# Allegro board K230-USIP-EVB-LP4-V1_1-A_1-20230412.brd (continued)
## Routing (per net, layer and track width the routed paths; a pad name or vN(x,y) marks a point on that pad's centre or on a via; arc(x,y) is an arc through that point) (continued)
MMC1_D0: length 64.5
  TOP w0.127: R123.1 24.89,99.57 24.89,101.22 25.78,102.11 27.43,102.11 27.81,102.49 v1(31.37,102.49) ; v1(68.2,83.19) 67.5,83.89 U4.7
  ART06 w0.127: v1(31.37,102.49) 32,101.85 32.89,101.85 40.13,94.61 63.75,94.61 69.09,89.28 69.09,84.07 v1(68.2,83.19)
  BOTTOM w0.127: R189.2 v1(68.2,83.19) 67.69,83.69 U23.2
MMC1_D1: length 66.4
  TOP w0.127: v1(68.2,81.92) 67.33,82.79 U4.8 ; v1(32.64,101.35) 32.13,100.84 29.59,100.84 R124.1
  ART06 w0.127: v1(68.2,81.92) 67.69,82.42 67.69,83.82 68.71,84.84 68.71,88.9 66.93,90.68 65.91,90.68 62.48,94.11 44.8,94.11 44.65,93.96 44.65,93.24 44.51,93.09 44.3,93.09 44.15,93.24 44.15,93.96 44,94.11 43.79,94.11 43.64,93.96 43.64,93.24 43.49,93.09 43.28,93.09 43.13,93.24 43.13,93.96 42.98,94.11 42.77,94.11 42.62,93.96 42.62,93.24 42.47,93.09 42.26,93.09 42.11,93.24 42.11,93.96 41.97,94.11 41.76,94.11 41.61,93.96 41.61,93.49 41.46,93.34 41.25,93.34 41.1,93.49 41.1,93.96 40.95,94.11 40.01,94.11 32.77,101.35 v1(32.64,101.35)
  BOTTOM w0.127: U23.3 67.69,81.41 v1(68.2,81.92) R190.2
MMC1_D2: length 66.4
  TOP w0.127: v1(67.96,91.31) 67.13,90.49 U4.1 ; R125.1 25.91,99.44 25.91,100.84 26.16,101.09 27.56,101.09 28.45,101.98 32,101.98 v1(32.51,102.49)
  ART06 w0.127: v1(32.51,102.49) 32.89,102.49 33.67,101.71 33.88,101.71 34.5,102.32 34.71,102.32 34.86,102.17 34.86,101.96 34.24,101.35 34.24,101.14 34.39,100.99 34.6,100.99 35.22,101.6 35.43,101.6 35.58,101.46 35.58,101.25 34.96,100.63 34.96,100.42 35.11,100.27 35.32,100.27 35.94,100.89 36.15,100.89 36.3,100.74 36.3,100.53 35.68,99.91 35.68,99.7 35.83,99.55 36.04,99.55 36.66,100.17 36.87,100.17 37.02,100.02 37.02,99.81 36.4,99.19 36.4,98.98 36.55,98.83 36.76,98.83 37.37,99.45 37.58,99.45 37.73,99.3 37.73,99.09 37.12,98.47 37.12,98.26 37.27,98.11 37.48,98.11 38.09,98.73 38.3,98.73 38.45,98.58 38.45,98.37 37.84,97.75 37.84,97.54 40.26,95.12 64.15,95.12 v1(67.96,91.31)
  BOTTOM w0.127: R191.2 68.08,91.44 v1(67.96,91.31) U24.2
MMC1_D3: length 67.1
  TOP w0.127: R126.1 28.96,101.35 v1(31.37,101.35) ; v1(67.82,88.9) 67.33,89.39 U4.2
  ART06 w0.127: v1(67.82,88.9) 66.55,90.17 65.79,90.17 62.36,93.6 51.74,93.6 51.59,93.45 51.59,92.48 51.44,92.33 51.22,92.33 51.07,92.48 51.07,93.45 50.92,93.6 50.7,93.6 50.55,93.45 50.55,92.48 50.4,92.33 50.18,92.33 50.03,92.48 50.03,93.45 49.88,93.6 49.66,93.6 49.51,93.45 49.51,92.48 49.36,92.33 49.14,92.33 48.99,92.48 48.99,93.45 48.84,93.6 48.62,93.6 48.47,93.45 48.47,92.48 48.32,92.33 48.1,92.33 47.95,92.48 47.95,93.45 47.79,93.6 47.58,93.6 47.43,93.45 47.43,92.48 47.27,92.33 47.01,92.33 46.86,92.48 46.86,93.2 46.71,93.34 46.5,93.34 46.35,93.2 46.35,92.48 46.2,92.33 45.99,92.33 45.84,92.48 45.84,93.2 45.69,93.34 45.48,93.34 45.33,93.2 45.33,92.48 45.18,92.33 41.15,92.33 32.77,100.71 32,100.71 v1(31.37,101.35)
  BOTTOM w0.127: U24.3 67.69,89.03 v1(67.82,88.9) R193.2 R147.2
MUTE: length 6.1
  TOP w0.127: TP25.1 62.48,121.16 62.36,121.03 R130.2 61.85,120.52 60.82,121.56 U16.6
NC_NC: length 3.3
  TOP w0.127: R207.2 1.91,38.1
OSPI_CLK: length 43.2
  TOP w0.127: J9.14 28.89,106.36 29.46,106.93 32.26,106.93 32.64,107.31 v1(32.64,113.67) ; U1.K1 28.9,92.02 29.72,92.84 29.72,94.54 v3(29.79,94.61)
  ART06 w0.127: v1(32.64,113.67) 30.99,113.67 30.61,113.28 30.61,109.73 29.95,109.07 29.95,97.13 29.22,96.41 29.22,95.19 v3(29.79,94.61)
OSPI_CS: length 43.9
  TOP w0.127: J9.6 23.18,118.3 25.65,115.82 25.65,111.38 26.29,110.74 27.18,110.74 v1(27.69,111.25) ; U1.J5 v2(29.22,83.26)
  ART06 w0.076: v2(29.22,83.26) 28.24,84.24 28.24,85.6
  ART06 w0.127: 28.24,85.6 28.24,86.39 28.3,86.44 28.3,87.25 27.18,88.37 27.18,97.54 28,98.36 28,108.65 27.69,108.97 v1(27.69,111.25)
OSPI_D0: length 43.3
  TOP w0.076: 29.23,86.49 29.23,85.86 U1.K2
  TOP w0.127: 29.23,86.49 29.23,91.58 30.35,92.71 30.35,95.38 v1(30.86,95.89) ; v1(32,107.57) 29.08,107.57 26.99,105.47 J9.13
  ART06 w0.127: v1(30.86,95.89) 30.77,95.97 30.77,102.91 30.92,103.06 34.27,103.06 34.42,103.21 34.42,103.42 34.27,103.57 30.92,103.57 30.77,103.72 30.77,103.93 30.92,104.08 33.38,104.08 33.53,104.23 33.53,104.44 33.38,104.59 30.92,104.59 30.77,104.74 30.77,105.03 30.9,105.16 31.88,105.16 32,105.28 v1(32,107.57)
OSPI_D1: length 43.4
  TOP w0.127: U1.K4 v2(29.22,84.56) ; v1(28.19,110.36) 26.04,110.36 25.02,111.38 25.02,115.82 21.27,119.57 J9.7
  ART06 w0.076: 28.83,86.11 28.7,85.98 28.7,84.84 28.98,84.56 v2(29.22,84.56)
  ART06 w0.127: 28.83,86.11 28.91,86.18 28.91,87.68 27.93,88.66 27.93,97.14 28.74,97.96 28.74,109.82 v1(28.19,110.36)
OSPI_D2: length 43.1
  TOP w0.127: J9.9 19.37,105.35 20.83,106.81 24,106.81 24.16,106.96 24.16,107.17 23.73,107.6 23.73,107.81 23.88,107.96 24.09,107.96 24.52,107.53 24.73,107.53 24.88,107.68 24.88,107.89 24.45,108.32 24.45,108.53 24.6,108.68 24.81,108.68 25.24,108.25 25.45,108.25 25.6,108.4 25.6,108.61 25.17,109.04 25.17,109.25 25.32,109.4 25.53,109.4 25.96,108.97 26.17,108.97 26.54,109.35 v1(28.19,109.35) ; U1.K5 v2(29.22,83.91)
  ART06 w0.076: v2(29.22,83.91) 28.49,84.65 28.49,86.14 28.57,86.23 28.57,86.36
  ART06 w0.127: v1(28.19,109.35) 28.36,109.18 28.36,98.21 27.56,97.41 27.56,88.52 28.57,87.5 28.57,86.36
OSPI_D3: length 43.1
  TOP w0.127: J9.3 28.89,120.59 29.21,120.27 v1(29.21,114.43) ; v1(28.71,94.61) 28.71,93.26 28.25,92.79 U1.L1
  ART06 w0.127: v1(28.71,94.61) 28.71,96.79 29.44,97.51 29.44,109.58 29.97,110.11 29.97,110.95 29.82,111.1 28.98,111.1 28.83,111.25 28.83,111.46 28.98,111.61 29.82,111.61 29.97,111.76 29.97,111.97 29.82,112.12 28.98,112.12 28.83,112.27 28.83,112.48 28.98,112.63 29.82,112.63 29.97,112.78 29.97,112.99 29.82,113.14 28.98,113.14 28.83,113.28 28.83,113.49 28.98,113.64 29.82,113.64 29.97,113.79 29.97,114.3 29.84,114.43 v1(29.21,114.43)
OSPI_D4: length 43.1
  TOP w0.076: 28.58,86.61 28.58,85.86 U1.L2
  TOP w0.127: J9.12 25.08,105.35 28.57,108.84 v1(32,108.84) ; 28.58,86.61 28.58,92.71 29.21,93.35 29.21,95.25 v1(29.84,95.89)
  ART06 w0.127: v1(32,108.84) 32,112.9 31.88,113.03 31.37,113.03 31.24,112.9 31.24,109.6 30.45,108.81 30.45,96.49 v1(29.84,95.89)
OSPI_D5: length 43
  TOP w0.127: v1(26.67,111.25) 26.16,111.76 26.16,115.95 25.08,117.03 25.08,117.79 25.23,117.94 25.76,117.94 25.91,118.08 25.91,118.3 25.76,118.44 25.23,118.44 25.08,118.59 25.08,118.8 25.23,118.95 25.76,118.95 25.91,119.1 25.91,119.31 25.76,119.46 25.23,119.46 25.08,119.61 25.08,119.82 25.23,119.97 25.76,119.97 25.91,120.12 25.91,120.33 25.76,120.48 25.23,120.48 25.08,120.62 J9.5 ; U1.L3 v2(27.93,85.21)
  ART06 w0.127: v1(26.67,111.25) 26.67,109.47 27.65,108.5 27.65,98.51 26.8,97.66 26.8,88.14 27.93,87.01 v2(27.93,85.21)
OSPI_D6: length 43.2
  TOP w0.127: U1.L4 v2(27.93,84.56) ; J9.10 21.27,106.11 21.46,106.3 21.72,106.3 21.87,106.15 21.87,105.81 22.02,105.66 22.23,105.66 22.38,105.81 22.38,106.15 22.53,106.3 22.74,106.3 22.88,106.15 22.88,105.81 23.03,105.66 23.24,105.66 23.39,105.81 23.39,106.15 23.54,106.3 24.45,106.3 v1(26.35,108.2)
  ART06 w0.076: v2(27.93,84.56) 27.93,84.72 27.6,85.05 27.6,85.47
  ART06 w0.127: 27.6,85.47 27.6,86.74 26.41,87.93 26.41,97.91 27.28,98.78 27.28,103.92 27.13,104.07 26.31,104.07 26.16,104.21 26.16,104.42 26.31,104.57 27.13,104.57 27.28,104.72 27.28,104.93 27.13,105.08 26.31,105.08 26.16,105.23 26.16,105.44 26.31,105.59 27.13,105.59 27.28,105.74 27.28,105.95 27.13,106.1 26.31,106.1 26.16,106.25 26.16,106.46 26.31,106.61 27.13,106.61 27.28,106.75 27.28,106.96 27.13,107.11 26.31,107.11 26.16,107.26 26.16,107.47 26.31,107.62 27.13,107.62 27.28,107.77 27.28,107.98 27.05,108.2 v1(26.35,108.2)
OSPI_D7: length 43.1
  TOP w0.127: v1(26.99,112.65) J9.4 ; U1.L5 v2(27.93,83.91)
  ART06 w0.076: v2(27.93,83.91) 27.93,84.01 27.6,84.34 27.6,84.7 27.3,84.99 27.3,85.34
  ART06 w0.127: v1(26.99,112.65) 26.99,113.22 26.8,113.41 26.04,113.41 25.78,113.16 25.78,103.76 25.91,103.63 26.8,103.63 26.92,103.5 26.92,98.93 26.01,98.02 26.01,87.78 27.3,86.49 27.3,85.34
OSPI_DQS: length 43.2
  TOP w0.127: U1.L6 v2(27.93,83.26) ; J9.11 v1(23.18,99.82)
  ART06 w0.076: v2(27.93,83.26) 27.59,83.6 27.59,84.04 27.39,84.24 27.14,84.24 26.94,84.44 26.94,85.58
  ART06 w0.127: 26.94,85.58 26.94,86.36 25.69,87.61 25.69,96.62 25.46,96.84 22.39,96.84 22.25,96.99 22.25,97.2 22.39,97.35 25.54,97.35 25.66,97.48 25.66,97.66 25.46,97.86 22.39,97.86 22.25,98.01 22.25,98.22 22.39,98.36 25.56,98.36 25.69,98.49 25.69,98.9 25.53,99.06 22.35,99.06 22.23,99.19 22.23,101.6 22.35,101.73 22.86,101.73 22.99,101.6 22.99,100.01 v1(23.18,99.82)
OTP_IO59: length 3.7
  TOP w0.127: U34.3 59.98,98.46 J22.2
OUT: length 4
  TOP w0.127: U29.4 TVS14.1 70.36,134.87 70.74,134.49 71.63,134.49
OUTL+: length 16.2
  TOP w0.127: U16.2 57.92,119.77 v1(57.53,119.38)
  BOTTOM w0.127: R82.1 62.22,129.92 60.46,129.92 57.02,126.48 57.02,119.89 v1(57.53,119.38)
OUTL-: length 18.8
  TOP w0.127: U16.5 59.42,119.78 v1(59.82,119.38)
  BOTTOM w0.127: R84.1 60.45,130.56 56.64,126.75 56.64,119.51 57.28,118.87 59.31,118.87 v1(59.82,119.38)
OUTR+: length 7.8
  TOP w0.127: R86.1 61.98,130.19 61.98,129.41 57.92,125.36 U16.14
OUTR-: length 7.4
  TOP w0.127: U16.11 59.42,125.08 59.94,125.6 59.94,126.87 62.48,129.41 62.48,130.18 R90.1
PW_EN: length 10.7
  TOP w0.254: C268.1 14.1,4.32 16.51,1.91 19.05,1.91
PWIN_FLASH: length 48.8
  TOP w0.127: J9.8 19.37,120.78 24.51,115.63 24.51,111.25 25.91,109.86 28.83,109.86 v1(29.34,110.36) ; U1.K7 v2(29.22,81.96)
  ART06 w0.127: v2(28.32,93.73) 28.22,93.83 28.22,96.8 29.08,97.66 29.08,110.11 v1(29.34,110.36)
  BOTTOM w0.127: v2(28.32,93.73) 27.81,93.22 27.81,86.49 27.94,86.36 C27.1 28.32,82.86 v2(29.22,81.96)
RESET_N_A_B: length 44
  TOP w0.089: U1.J16 v2(29.87,76.11)
  ART03 w0.086: v2(29.87,76.11) 29.87,75.67 29.34,75.14 28.45,75.14 28.25,74.94 28.25,72.66 28.65,72.26 28.65,49.01 v2(27.83,48.18) 28.14,47.87 39.41,47.87 v2(39.73,48.18)
  BOTTOM w0.086: R64.2 27.83,48.15 v2(27.83,48.18) ; v2(39.73,48.18) 39.88,48.03 R68.2
RTC_1V8: length 123.9
  TOP w0.254: U1.F15 v2(31.82,77.41) U1.F14
  TOP w0.381: R262.2 v1(71.25,25.91) ; R62.2 17.78,3.81 18.41,3.17 22.86,3.17 24.13,1.91 26.67,1.91 27.94,3.17 30.48,3.17 31.75,1.91
  TOP w0.508: v1(49.78,55.12) 47.55,57.35
  ART06 w0.508: v1(49.78,55.12) 50.47,54.43 63.55,54.43 72.95,45.03 72.95,30.66 71.25,28.96 v1(71.25,25.91) 71.25,25.15 63.37,17.27 49.53,17.27 35.43,3.17 33.02,3.17 31.75,1.91
  vias: v1(44.45,58.42) v1(45.72,58.42) v1(45.72,57.15)
RTC_CLK_IN: length 16
  TOP w0.076: U1.B12 34.42,79.36 34.92,79.36
  TOP w0.127: 47.37,74.68 40.44,74.68 38.61,76.5 38.61,77.62 36.87,79.36 34.92,79.36
RTC_CLK_OUT: length 15.8
  TOP w0.127: U1.A12 36.83,79.04 38.23,77.64 38.23,76.16 40.22,74.17 46.61,74.17 47.37,73.41
RTC_INT0: length 93.1
  TOP w0.102: U1.C10 33.77,80.01 v2(33.77,79.36)
  TOP w0.127: v1(35.94,11.18) TVS1.1 34.42,10.41 34.04,10.03
  ART06 w0.127: v2(33.77,79.36) 34.17,79.76 38.61,79.76 40.25,78.12 42.41,78.12 42.8,77.72 46.61,77.72 47.75,76.58 47.75,75.31 49.28,73.79 49.28,71.25 50.29,70.23 50.29,58.8 48.44,56.95 48.44,47.29 47.75,46.61 47.75,44.96 46.35,43.56 46.35,41.53 45.97,41.15 45.17,41.15 43.39,39.37 41.15,39.37 38.48,36.7 38.48,13.72 v1(35.94,11.18)
RTC_INT1: length 93.4
  TOP w0.076: U1.B10 34.42,80.66 35.05,80.66
  TOP w0.127: 31.75,10.03 32.13,10.41 TVS2.1 v1(32.89,11.18) ; 35.05,80.66 37.15,80.66 37.71,80.1 38.6,80.1 39.12,79.58 39.12,78.99 40.39,77.72 40.39,77.39 41.33,76.45 44.96,76.45 v3(45.59,77.09)
  ART06 w0.127: v1(32.89,11.18) 34.54,11.18 37.97,14.61 37.97,36.96 41.66,40.64 42.98,40.64 47.37,45.03 47.37,46.74 48.13,47.5 48.13,57.15 49.91,58.93 49.91,70.07 49,70.98 49,73.56 47.37,75.18 47.37,76.45 46.74,77.09 v3(45.59,77.09)
RTC_INT2: length 93.8
  TOP w0.127: v3(46.61,76.45) 45.47,76.45 45.09,76.07 41.02,76.07 39.88,77.22 39.88,77.72 38.73,78.87 38.73,79.5 38.46,79.78 37.64,79.78 37.09,80.34 U1.A10 ; v1(30.48,11.18) TVS6.1 29.59,10.41 29.21,10.03
  ART06 w0.127: v1(30.48,11.18) 31.11,11.81 34.42,11.81 37.47,14.86 37.47,37.08 41.53,41.15 43,41.15 47.03,45.17 47.03,47.03 47.75,47.75 47.75,57.28 49.53,59.05 49.53,69.98 48.72,70.79 48.72,73.33 47.05,74.99 47.05,76.01 v3(46.61,76.45)
RTC_INT3: length 94.8
  TOP w0.127: 26.67,10.03 27.05,10.41 TVS7.1 v1(27.94,11.18) ; v3(46.61,75.56) 46.28,75.23 40.6,75.23 39.03,76.81 39.03,77.57 36.91,79.69 U1.A11
  ART06 w0.127: v3(46.61,75.56) 46.61,74.93 48.39,73.15 48.39,70.61 49.19,69.81 49.19,59.22 47.41,57.44 47.41,47.92 46.67,47.18 46.67,45.28 43.05,41.66 41.4,41.66 36.96,37.21 36.96,14.99 34.16,12.19 28.96,12.19 v1(27.94,11.18)
RTC_INT4: length 95.7
  TOP w0.076: U1.C12 33.77,78.71 35.69,78.71
  TOP w0.127: 24.13,10.03 24.51,10.41 TVS8.1 v1(25.4,13.34) ; v3(46.35,73.41) 46.1,73.66 39.92,73.66 37.72,75.86 37.72,77.77 36.78,78.71 35.69,78.71
  ART06 w0.127: v1(25.4,13.34) 33.27,13.34 35.43,15.49 35.43,37.59 41.02,43.18 42.16,43.18 42.42,43.43 42.42,44.45 46.45,48.48 46.45,58.13 47.49,59.17 47.49,71.13 46.74,71.88 46.74,73.03 v3(46.35,73.41)
RTC_INT5: length 100.8
  TOP w0.127: 21.59,10.03 21.97,10.41 TVS9.1 v1(22.86,11.18) ; v2(33.12,78.71) 32.8,79.03 U1.D12
  ART06 w0.127: v2(33.12,78.71) 34.01,78.71 34.79,79.49 38.37,79.49 41.34,76.52 45.53,76.52 46.1,75.95 46.1,74.93 48.04,72.99 48.04,70.45 48.77,69.72 48.77,59.31 47.12,57.66 47.12,48.13 46.35,47.37 46.35,45.38 43.14,42.16 41.27,42.16 36.45,37.34 36.45,15.11 33.91,12.57 28.07,12.57 26.67,11.18 v1(22.86,11.18)
RTC_OUT0: length 102.1
  TOP w0.076: U1.B11 34.42,80.01 34.92,80.01
  TOP w0.127: v3(45.59,75.69) 40.77,75.69 39.5,76.96 39.5,77.62 38.35,78.77 38.35,79.34 38.23,79.46 37.58,79.46 37.03,80.01 34.92,80.01 ; v1(20.32,11.18) TVS10.1 19.43,10.41 19.05,10.03 17.78,10.03
  ART06 w0.127: v3(45.59,75.69) 45.59,74.93 47.76,72.76 47.76,58.94 46.79,57.96 46.79,48.31 44.07,45.59 44.07,43.81 42.93,42.67 41.15,42.67 35.94,37.47 35.94,15.37 33.53,12.95 27.56,12.95 26.67,12.06 21.21,12.06 v1(20.32,11.18)
RTC_OUT1: length 62.6
  TOP w0.127: U1.C11 v2(33.12,79.36)
  ART06 w0.127: v2(33.12,79.36) 33.77,80.01 39.24,80.01 40.14,79.11 48.27,79.11 50.67,76.71 56.39,76.71 62.36,70.74 62.36,70.1 63.37,69.09 63.37,62.1 65.41,60.07 66.67,60.07 67.56,59.18 67.56,53.59 71.25,49.91 v1(73.79,49.91)
  BOTTOM w0.127: v1(73.79,49.91) R22.1
SDL: length 5.9
  TOP w0.127: U16.7 61.33,122.06 61.59,121.79 R80.2 62.36,122.3 62.48,122.43 65.28,122.43 TP26.1
SDR: length 6.1
  TOP w0.127: U16.8 61.85,122.56 R132.2 62.36,123.57 62.48,123.7 65.02,123.7 TP27.1
SP_L: length 25.5
  TOP w0.127: C309.1 51.56,121.16 48.51,118.11 48.51,99.69 J20.1
SP_R: length 30
  TOP w0.127: C311.1 48.01,118.36 48.01,97.66 J21.1
SYS_CLK_IN: length 15.2
  TOP w0.076: U1.B8 34.42,81.96 35.05,81.96
  TOP w0.127: 47.37,80.26 46.99,79.88 46.39,79.88 45.89,80.39 45.89,81.24 44.82,82.31 39.38,82.31 39.14,82.07 35.84,82.07 35.73,81.96 35.05,81.96
SYS_CLK_OUT: length 14.3
  TOP w0.127: U1.A8 36.3,81.64 36.46,81.8 44.56,81.8 45.38,80.99 45.38,80.18 46.18,79.38 46.99,79.38 47.37,78.99
SYS_ON_OFF: length 52.5
  TOP w0.127: v1(72.26,22.23) 72.26,23.15 K1.1
  ART06 w0.127: 34.29,1.91 35.56,1.91 50.04,16.38 66.42,16.38 v1(72.26,22.23)
SYS_RST: length 70.6
  TOP w0.076: U1.B9 34.42,81.31 35.05,81.31
  TOP w0.127: 35.05,81.31 37.44,81.31 37.68,81.06 39.78,81.06 40.01,81.29 44.31,81.29 44.83,80.77 44.83,79.92 46.43,78.32 v1(46.58,78.32) ; K2.2 v1(76.83,47.75)
  ART06 w0.127: v1(46.58,78.32) 46.77,78.32 48.86,76.24 48.86,74.97 49.78,74.04 49.78,71.5 50.16,71.12 60.58,71.12 62.87,68.83 62.87,61.85 65.24,59.47 66.51,59.47 67.06,58.93 67.06,53.34 72.64,47.75 v1(73.91,47.75)
  BOTTOM w0.127: v1(73.91,47.75) R223.1 74.8,48.9 75.82,48.9 76.2,48.51 TVS3.1 v1(76.83,47.75)
SYS_SW: length 1.4
  TOP w0.127: 15.24,10.03 15.62,10.41 TVS11.1
TEST_EN: length 15.6
  TOP w0.127: 47.37,76.58 47.37,77.72 46.3,77.72 44.32,79.71 44.32,80.52 44.06,80.78 37.58,80.78 37.38,80.99 U1.A9
TOUCH_INT: length 18.5
  TOP w0.127: R182.1 6.22,84.45 4.95,83.19 3.3,83.19 2.35,84.14 2.35,89.98 5.78,93.41 7.09,93.41 7.09,93.41 J4.10
TOUCH_RST: length 20
  TOP w0.127: R183.1 6.48,82.55 3.18,82.55 1.84,83.88 1.84,90.2 5.56,93.91 7.09,93.91 7.09,93.91 J4.11
U_3V3: length 1.7
  TOP w0.305: 58.04,92.08 57.4,92.08 57.02,91.69 57.02,91.19
UART0_RXD: length 57.6
  TOP w0.127: R54.2 v1(50.29,124.33) ; v1(65.53,116.71) 65.53,116.84 65.69,116.99 U25.6
  ART06 w0.127: v1(50.29,124.33) 49.78,123.83 46.61,123.83 40.01,117.22 40.01,116.46 38.86,115.32 38.86,108.33 v1(38.61,108.08)
  BOTTOM w0.127: v1(65.53,116.71) 64.44,117.81 55.42,117.81 50.29,122.94 v1(50.29,124.33) ; v1(38.61,108.08) 36.07,108.08 33.27,105.28 33.27,104.14 32,102.87 32,99.19 R94.2
UART0_RXD_3V3: length 7.4
  TOP w0.127: U26.16 66.42,112.23 68.78,114.59 68.78,116.64 68.43,116.99 U25.9
UART0_TXD: length 57.5
  TOP w0.127: R53.2 v1(49.15,124.33) ; v1(38.1,106.93) 35.94,106.93 33.91,104.9 33.91,100.58 R92.2 ; U25.5 65.2,117.39 v1(64.64,116.84)
  ART06 w0.127: v1(49.15,124.33) 46.48,124.33 38.48,116.33 38.48,110.36 38.1,109.98 v1(38.1,106.93)
  BOTTOM w0.127: v1(49.15,124.33) 49.15,123.06 54.86,117.35 64.14,117.35 v1(64.64,116.84)
UART0_TXD_3V3: length 9.5
  TOP w0.127: v1(68.2,114.81) 67.31,113.92 64.77,113.92 64.46,113.61 U26.17 ; U25.10 68.53,117.39 69.47,116.46 v1(69.47,114.81)
  BOTTOM w0.127: v1(69.47,114.81) v1(68.2,114.81)
UART3_CTS_FT: length 2.1
  TOP w0.127: U36.10 55.19,108.77 55.23,108.73 U26.40
UART3_RTS_FT: length 2.1
  TOP w0.127: U26.41 55.35,108.23 55.21,108.37 U36.9
UART3_RXD: length 94.6
  TOP w0.127: v1(13.46,71.5) 10.16,68.2 R141.2 ; U36.3 51.98,109.57 51.31,110.24 v1(51.31,110.49)
  ART06 w0.127: v1(26.42,100.58) 24.64,102.36 24.64,114.14 26.83,116.33 v1(27.94,116.33)
  BOTTOM w0.127: v1(51.31,110.49) 50.04,111.76 50.04,113.89 45.66,118.27 30.64,118.27 28.7,116.33 v1(27.94,116.33) ; v1(13.46,71.5) 14.03,72.07 14.03,73.14 20.32,79.43 20.32,98.42 22.86,100.97 26.04,100.97 v1(26.42,100.58) 27.69,99.31 R117.1
UART3_RXD_FT: length 2.1
  TOP w0.127: U26.38 55.37,109.73 55.21,109.57 U36.12
UART3_TXD: length 97.1
  TOP w0.127: U36.4 51.62,109.17 v1(51.31,109.47) ; R144.2 9.78,67.06 14.61,71.88 v1(14.61,72.39)
  ART06 w0.127: v1(26.42,99.69) 24.26,101.85 24.26,114.43 27.18,117.35 v1(28.7,117.35)
  BOTTOM w0.127: v1(51.31,109.47) 51.94,110.11 51.94,110.74 50.42,112.27 50.42,114.05 45.82,118.65 30,118.65 v1(28.7,117.35) ; v1(14.61,72.39) 14.61,73.02 20.78,79.2 20.78,98.25 22.99,100.46 25.65,100.46 v1(26.42,99.69) 26.54,99.57 R115.1
UART3_TXD_FT: length 2.1
  TOP w0.127: U26.39 55.38,109.23 55.32,109.17 U36.11
USB0_DN: length 61.4
  TOP w0.102: U1.B2 34.42,85.86 35.18,85.86
  TOP w0.14: 35.18,85.86 37.94,88.61 41.54,88.61 v3(41.66,88.73) ; 71.46,73.53 71.46,72.8 71.73,72.53 J11.B7 ; 71.46,73.53 71.38,73.61 71.07,73.61 70.06,72.6 67.77,72.6 67.63,72.46 ; 71.46,73.53 72.53,73.53 J11.A7 ; 67.63,72.46 U32.3 ; 67.63,72.46 67.49,72.6 66.42,72.6 v1(66.17,72.35)
  ART06 w0.14: v1(66.17,72.35) 66.38,72.56 67.07,72.56 67.82,73.31 67.82,79.12 66.85,80.09 66.85,85.77 63.34,89.28 54.86,89.28 53.73,90.42 44.22,90.42 42.45,88.65 41.74,88.65 v3(41.66,88.73)
USB0_DP: length 62.4
  TOP w0.14: J11.A6 73.38,73.03 73.52,73.17 73.52,73.89 73.38,74.03 J11.B6 71.62,74.03 71.54,73.95 70.93,73.95 69.92,72.94 67.77,72.94 67.63,73.08 ; U1.A2 34.76,85.52 35.32,85.52 36.04,86.24 36.35,86.24 36.64,86.53 36.64,86.84 38.08,88.27 38.47,88.27 38.73,88.01 39.03,88.01 39.29,88.27 39.59,88.27 39.85,88.01 40.14,88.01 40.41,88.27 41.52,88.27 41.66,88.13 v3(41.66,87.97) ; v1(66.17,73.36) 66.59,72.94 67.49,72.94 67.63,73.08 ; 67.63,73.08 U32.2
  ART06 w0.14: v1(66.17,73.36) 66.17,73.15 66.42,72.9 66.93,72.9 67.48,73.45 67.48,73.95 67.32,74.11 67.12,74.11 66.95,74.27 66.95,74.5 67.12,74.67 67.32,74.67 67.48,74.83 67.48,78.98 66.51,79.95 66.51,85.63 63.2,88.94 54.72,88.94 53.59,90.08 44.36,90.08 42.59,88.31 41.8,88.31 41.66,88.17 v3(41.66,87.97)
USB0_ID: length 59.1
  TOP w0.127: U1.D3 v2(33.12,85.21) ; v1(66.17,75.69) U33.3 67.63,76.58 67.75,76.71 69.98,76.71 71.66,75.03 J11.B5 73.43,75.03 74.3,74.17 74.3,72.77 73.55,72.03 J11.A5
  ART06 w0.127: v2(33.12,85.21) 35.16,87.25 43.43,87.25 45.59,89.41 48.26,89.41 51.44,86.23 63.5,86.23 65.79,83.95 65.79,78.61 66.17,78.23 v1(66.17,75.69)
USB0_OTG_EN: length 116.4
  TOP w0.127: U3.4 66.74,69.41 v1(66.42,69.09) 65.91,68.58 v1(62.23,68.58)
  ART06 w0.127: v1(42.42,38.86) 43.37,38.86 45.28,40.77 46.86,40.77 47.62,41.53 47.62,43.43 48.01,43.81 48.51,43.81 48.77,44.07 48.77,56.64 50.42,58.29 51.05,58.29 51.44,58.67 51.44,59.82 55.24,63.63 57.28,63.63 v1(62.23,68.58)
  BOTTOM w0.127: v1(42.42,38.86) 21.59,38.86 13.46,46.99 13.46,61.09 5.71,68.83 3.94,68.83 3.3,69.47 3.3,76.07 J5.1 ; R41.1 v1(66.42,69.09)
USB0_OTG_VBUS: length 6.1
  TOP w0.381: U3.1 v1(68.96,67.5)
  BOTTOM w0.381: v1(71.12,70.74) 71.12,69.66 v1(68.96,67.5) 68.77,67.69 C17.1
USB0_VBUS: length 15.6
  TOP w0.254: U1.C3 v2(33.77,85.21)
  ART06 w0.254: v2(33.77,85.21) 35.28,86.72 43.42,86.72 44.97,88.27 45.72,88.27 v1(46.35,87.63)
  BOTTOM w0.254: 47.37,87.5 46.48,87.5 v1(46.35,87.63)
USB1_DN: length 63.6
  TOP w0.14: J13.A7 71.33,61.46 ; 71.33,61.46 71.33,60.8 71.67,60.46 J13.B7 ; 71.33,61.46 71.25,61.55 70.93,61.55 69.91,62.57 67.77,62.57 67.63,62.43 ; 67.63,62.43 U31.3 ; 67.63,62.43 67.49,62.57 66.38,62.57 66.17,62.36 v1(66.17,62.19) ; U1.A4 34.76,84.22 36.98,84.22 38.45,85.69 42.77,85.69 42.97,85.89 43.2,85.89 43.33,85.77 43.52,85.77 43.72,85.97 43.72,86.16 43.6,86.29 43.6,86.52 43.86,86.78 44.56,86.78 44.91,86.43 v3(44.91,86.32)
  ART06 w0.14: v3(44.91,86.32) 45.21,86.62 46.63,86.62 47.49,85.77 49.52,85.77 50.79,84.5 60.41,84.5 64.05,80.86 64.05,72.85 65.16,71.75 65.16,62.9 65.49,62.57 65.99,62.57 66.17,62.39 v1(66.17,62.19)
USB1_DP: length 64.3
  TOP w0.102: U1.B4 34.42,84.56 35.19,84.56
  TOP w0.14: J13.A6 73.39,60.96 73.53,61.1 73.53,61.82 73.39,61.96 J13.B6 71.62,61.96 71.54,61.88 71.07,61.88 70.05,62.91 67.77,62.91 67.63,63.05 ; 35.19,84.56 36.84,84.56 38.31,86.03 42.63,86.03 43.72,87.12 44.7,87.12 v3(44.91,87.33) ; 67.63,63.05 U31.2 ; 67.63,63.05 67.49,62.91 66.47,62.91 v1(66.17,63.2)
  ART06 w0.14: v3(44.91,87.33) 44.91,87.13 45.09,86.96 46.77,86.96 47.62,86.11 49.66,86.11 50.93,84.84 60.55,84.84 64.39,81 64.39,72.99 65.49,71.89 65.49,63.04 65.63,62.9 65.87,62.9 v1(66.17,63.2)
USB1_ID: length 73.6
  TOP w0.076: U1.B3 34.42,85.21 35.31,85.21
  TOP w0.127: v1(65.15,77.98) U33.2 67.63,78.74 67.88,78.99 74.68,78.99 76.07,77.6 76.07,64.97 74.07,62.96 ; 74.07,62.96 74.55,62.48 74.55,60.58 73.93,59.96 J13.A5 ; 74.07,62.96 J13.B5 ; v1(46.35,88.9) 43.69,88.9 42.04,87.25 38.35,87.25 36.31,85.21 35.31,85.21
  ART06 w0.127: v1(46.35,88.9) 48.39,86.87 50.29,86.87 51.31,85.85 60.96,85.85 65.15,81.66 v1(65.15,77.98)
USB1_OTG_EN: length 109.9
  TOP w0.127: v1(66.29,58.8) 66.74,59.25 U6.4
  ART06 w0.127: v1(66.29,58.8) 66.04,58.55 52.7,58.55 51.18,57.02 50.42,57.02 49.28,55.88 49.28,46.99 49.78,46.48 49.78,42.55 48.51,41.27 47.88,41.27 46.99,40.39 45.47,40.39 43.43,38.35 v1(41.02,38.35)
  BOTTOM w0.127: v1(41.02,38.35) 21.38,38.35 12.95,46.78 12.95,60.83 5.46,68.33 3.68,68.33 2.92,69.09 2.92,73.91 1.91,74.93 ; v1(66.29,58.8) 66.04,59.05 R46.1
USB1_OTG_VBUS: length 9.6
  TOP w0.381: U6.1 v1(69.02,57.34)
  BOTTOM w0.381: v1(71.12,63.63) v1(71.12,58.8) 69.66,57.34 v1(69.02,57.34) 68.71,57.66 C21.1
USB1_VBUS: length 14.3
  TOP w0.254: U1.A3 36.5,84.89 38.44,86.83 42.25,86.83 43.69,88.27 46.61,88.27 47.37,87.5
VCM: length 2.3
  TOP w0.254: U1.F3 v2(31.17,84.56)
  BOTTOM w0.305: C149.1 30.99,84.75 v2(31.17,84.56)
VSY0: length 8.3
  TOP w0.127: J3.53 45.76,128.61 47,127.37 49.29,127.37 R54.1 R52.2
VTEST: length 15.6
  TOP w0.127: U1.D8 v2(33.12,81.96) ; V-TS.1 v1(46.48,80.64)
  ART06 w0.127: v1(46.48,80.64) 46.35,80.77 41.02,80.77 40.01,81.79 33.3,81.79 v2(33.12,81.96)
N20962780: length 3.6
  TOP w0.254: Y1.1 50.43,73.79 49.91,73.79 C3.1 R5.2
N20962782: length 3.7
  TOP w0.254: Y1.2 50.39,74.25 49.96,74.25 C4.1 R6.1
N20963869: length 2.7
  TOP w0.127: SW1.3 v1(70.48,46.48)
  BOTTOM w0.127: R13.1 v1(70.48,46.48)
N20963881: length 2.7
  TOP w0.127: 67.94,44.89 v1(67.94,46.48)
  BOTTOM w0.127: R14.1 v1(67.94,46.48)
N20968799: length 2.2
  TOP w0.089: U1.K19 v2(28.58,74.16)
  BOTTOM w0.127: R61.1 27.69,73.27 v2(28.57,74.16)
N20974230: length 16.5
  TOP w0.127: v1(46.48,85.22) 46.48,85.47 47.37,86.36 ; U1.D4 v2(33.12,84.56)
  ART06 w0.076: v2(33.12,84.56) 33.44,84.87 33.95,84.87
  ART06 w0.127: 33.95,84.87 34.18,84.87 35.67,86.36 43.94,86.36 44.83,85.47 46.23,85.47 v1(46.48,85.22)
N20974244: length 15.4
  TOP w0.127: U1.C4 v2(33.77,84.56) ; v1(45.09,84.86) 45.22,84.72 46.88,84.72 47.37,85.22
  ART06 w0.127: v2(33.77,84.56) 34.41,84.56 35.83,85.98 43.69,85.98 44.81,84.86 v1(45.09,84.86)
N20974837: length 2.1
  TOP w0.254: U3.3 69.02,69.41 v1(68.96,69.34)
  BOTTOM w0.254: R40.2 68.71,69.09 v1(68.96,69.34)
N20975021: length 2
  TOP w0.254: U6.3 v1(68.96,59.25)
  BOTTOM w0.254: R45.2 68.77,59.05 v1(68.96,59.25)
N20990724: length 3.3
  TOP w0.254: R10.1 C11.1 49.78,80.01 50.55,80.01 Y3.3
N20990759: length 5.2
  TOP w0.254: R8.1 C8.1 50.04,79.5 52.07,79.5 52.87,78.7 Y3.1
N21006529: length 2.8
  TOP w0.127: U1.U6 v2(24.03,83.26)
  BOTTOM w0.127: R65.2 23.5,84.45 24.03,83.92 v2(24.03,83.26)
N21013358: length 17.2
  TOP w0.076: 20,78.06 22.73,78.06 U1.W14
  TOP w0.127: R77.2 8.76,73.41 14.29,73.41 18.94,78.06 20,78.06
N21013362: length 22.5
  TOP w0.127: U1.U12 v2(24.03,79.36) ; v1(10.92,72.77) 9.78,71.63 R79.2
  ART06 w0.076: 22.54,79.95 23.01,79.48 23.76,79.48 23.88,79.36 v2(24.03,79.36)
  ART06 w0.127: 22.54,79.95 22.22,80.26 16.76,80.26 16.26,79.76 15.24,79.76 13.46,77.98 12.32,77.98 11.68,77.34 11.68,75.82 10.92,75.06 v1(10.92,72.77)
N21013366: length 22.4
  TOP w0.127: U1.T13 v2(24.68,78.71)
  ART06 w0.076: 22.35,79.76 22.85,79.26 23.66,79.26 23.89,79.03 24.35,79.03 v2(24.68,78.71)
  ART06 w0.127: 22.35,79.76 22.23,79.88 17.02,79.88 16.51,79.38 15.37,79.38 13.34,77.34 v1(12.45,77.34)
  BOTTOM w0.127: R81.2 7.11,81.53 7.37,81.28 9.78,81.28 11.81,79.25 11.81,77.98 v1(12.45,77.34)
N21013370: length 18.5
  TOP w0.127: U1.U13 v2(24.03,78.71) ; R83.2 8.76,76.71 12.06,76.71 v1(12.57,76.2)
  ART06 w0.076: v2(24.03,78.71) 23.91,78.71 23.58,79.03 22.73,79.03 22.53,79.24
  ART06 w0.127: 22.53,79.24 22.26,79.5 17.14,79.5 16.69,79.04 15.54,79.04 12.7,76.2 v1(12.57,76.2)
N21013374: length 17.3
  TOP w0.127: R85.2 9.4,70.48 11.81,72.9 14.24,72.9 19.08,77.74 U1.Y14
N21013378: length 16.6
  TOP w0.127: R87.2 8.64,77.98 14.61,77.98 v3(15.37,77.22) ; U1.V13 v2(23.38,78.06)
  ART06 w0.127: v3(15.37,77.22) 15.37,77.23 16.17,78.03 23.35,78.03 v2(23.38,78.06)
N21013382: length 20
  TOP w0.127: R89.2 v1(11.05,76.2) ; U1.T12 v2(24.68,79.36)
  ART06 w0.076: v2(24.68,79.36) 24.34,79.69 23.18,79.69 22.8,80.07
  ART06 w0.127: v1(11.05,76.2) 11.05,77.34 12.19,78.49 13.49,78.49 15.09,80.09 16.08,80.09 16.64,80.64 22.22,80.64 22.8,80.07
N21014154: length 18.4
  TOP w0.127: R116.1 9.4,78.36 14.99,78.36 v3(16.13,77.22) ; U1.T14 v2(24.68,78.06)
  ART06 w0.076: 23.04,77.74 24.35,77.74 v2(24.68,78.06)
  ART06 w0.127: 23.04,77.74 16.65,77.74 v3(16.13,77.22)
N21014156: length 20.3
  TOP w0.127: R118.1 8.89,69.34 11.94,72.39 v1(13.46,72.39) ; U1.U15 v2(24.68,77.41)
  ART06 w0.076: v2(24.68,77.41) 24.35,77.09 22.98,77.09
  ART06 w0.127: v1(13.46,72.39) 18.16,77.09 22.98,77.09
N21014379: length 15.1
  TOP w0.127: v1(30.86,93.47) 31.37,93.98 31.37,97.03 R92.1 ; U1.J4 v2(29.87,84.56)
  ART06 w0.076: 29.55,85.81 29.55,85 29.87,84.68 v2(29.87,84.56)
  ART06 w0.127: 29.55,85.81 29.55,90.26 30.86,91.57 v1(30.86,93.47)
N21014381: length 14.2
  TOP w0.127: U1.J3 v2(29.87,85.21)
  ART06 w0.127: v2(29.87,85.21) 29.87,89.95 31.37,91.44 31.37,95.38 v1(31.88,95.89)
  BOTTOM w0.127: R94.1 31.88,97.54 v1(31.88,95.89)
N21014383: length 14.5
  TOP w0.076: U1.J2 29.88,85.86 29.88,86.49
  TOP w0.127: 29.88,86.49 29.88,90.2 34.54,94.87 R96.1
N21014385: length 13.3
  TOP w0.127: R98.1 33.4,94.23 29.55,90.38 U1.J1
N21014387: length 14
  TOP w0.127: R100.1 35.69,95.47 30.2,89.98 U1.H1
N21014389: length 19.6
  TOP w0.127: 47.37,84.07 v1(46.35,84.07) ; U1.J6 v2(29.87,83.26)
  ART06 w0.102: 34.16,84.23 32.67,84.23 32.02,83.59 30.2,83.59 v2(29.87,83.26)
  ART06 w0.127: 34.16,84.23 34.58,84.23 35.97,85.62 42.27,85.62 43.31,84.58 44.2,84.58 44.45,84.33 46.1,84.33 v1(46.35,84.07)
N21014391: length 15.1
  TOP w0.076: U1.H2 30.53,85.86 30.53,86.55
  TOP w0.127: 30.53,86.55 30.53,89.83 36.83,96.14 R104.1
N21014393: length 15.3
  TOP w0.127: U1.H3 v2(30.52,85.21)
  ART06 w0.127: v2(30.52,85.21) 30.52,88.31 32.38,90.17 32.38,95.12 32.64,95.38 33.4,95.38 33.91,95.89 v1(33.91,96.27)
  BOTTOM w0.127: v1(33.91,96.27) 33.91,97.28 R106.1
N21014395: length 17.6
  TOP w0.127: U1.H4 v2(30.52,84.56)
  ART06 w0.076: v2(30.52,84.56) 30.52,84.75 30.86,85.09 30.86,85.47
  ART06 w0.127: 30.86,85.47 30.86,88.14 32.89,90.17 v1(32.89,94.87)
  BOTTOM w0.127: R108.1 36.83,97.28 34.04,94.49 33.27,94.49 v1(32.89,94.87)
N21014397: length 16.4
  TOP w0.127: U1.H5 v2(29.87,83.91)
  ART06 w0.076: v2(29.87,83.91) 29.55,84.23 29.55,84.68 29.34,84.9 29.02,84.9 28.91,85.01 28.91,85.8 29.02,85.91
  ART06 w0.127: 29.02,85.91 29.21,86.11 29.21,92.96 v1(30.86,94.61)
  BOTTOM w0.127: R110.1 30.35,97.16 30.35,95.12 v1(30.86,94.61)
N21014399: length 16.1
  TOP w0.127: U1.G4 v2(30.53,83.91)
  ART06 w0.076: 30.19,85.89 30.19,84.25 v2(30.53,83.91)
  ART06 w0.127: 30.19,85.89 30.19,89.75 31.75,91.31 31.75,95 32.64,95.89 v1(32.89,95.89)
  BOTTOM w0.127: R112.1 32.89,97.41 v1(32.89,95.89)
N21014401: length 16.6
  TOP w0.127: U1.G5 v2(31.17,83.91)
  ART06 w0.076: v2(31.17,83.91) 30.85,84.24 30.85,84.77 31.11,85.04 31.11,85.22
  ART06 w0.127: v1(33.91,95.12) 33.91,90.42 31.11,87.63 31.11,85.22
  BOTTOM w0.127: R114.1 35.69,96.9 v1(33.91,95.12)
N21015109: length 18.7
  TOP w0.127: v2(27.28,83.26) 27.6,83.58 U1.M5
  ART06 w0.076: v2(27.28,83.26) 26.95,83.59 26.27,83.59 25.67,84.19 25.67,84.96
  ART06 w0.127: 25.67,84.96 25.67,85.46 23.37,87.76 23.37,95 v3(24.13,95.76)
  BOTTOM w0.127: R115.2 25.59,96.96 25.08,96.96 24.13,96.01 v3(24.13,95.76)
N21015111: length 18.2
  TOP w0.127: U1.M4 v2(27.28,83.91)
  ART06 w0.076: v2(27.28,83.91) 27.08,83.91 26.75,84.24 26.25,84.24 25.95,84.54 25.95,85.09
  ART06 w0.127: v3(24.13,94.49) 24.13,87.63 25.95,85.81 25.95,85.09
  BOTTOM w0.127: v3(24.13,94.49) 24.64,95 24.64,95.89 25.27,96.52 26.29,96.52 R117.2
N21015121: length 17.2
  TOP w0.076: v2(26.63,85.21) 27.28,85.21 U1.M3
  ART06 w0.127: v2(26.63,85.21) 26.63,86.15 25.15,87.63 v3(25.15,94.49)
  BOTTOM w0.127: R119.2 26.54,94.49 v3(25.15,94.49)
N21015123: length 17.3
  TOP w0.127: U1.N4 v2(26.63,84.56)
  ART06 w0.127: v3(25.15,95.76) 24.64,95.25 24.64,87.63 26.26,86 26.26,84.92 v2(26.63,84.56)
  BOTTOM w0.127: R120.2 26.67,95.76 v3(25.15,95.76)
N21015125: length 13.8
  TOP w0.076: U1.M2 27.93,85.86 27.93,86.61
  TOP w0.127: 27.93,86.61 27.93,94.73 R121.2
N21015127: length 13.2
  TOP w0.076: 27.28,86.61 27.28,85.86 U1.N2
  TOP w0.127: 27.28,86.61 27.28,96.36 R122.2
N21015129: length 13.9
  TOP w0.076: U1.P3 25.98,85.21 25.98,86.55
  TOP w0.127: 25.98,86.55 25.98,96.2 R123.2
N21015131: length 12
  TOP w0.127: U1.N1 26.95,97.18 R124.2
N21015133: length 12.1
  TOP w0.127: R125.2 26.3,97.02 U1.P1
N21015135: length 12.6
  TOP w0.076: U1.P2 26.63,85.86 26.63,86.61
  TOP w0.127: R126.2 26.63,97.83 26.63,86.61
N21015137: length 17.7
  TOP w0.127: v2(25.33,83.91) 25.65,83.59 U1.P5
  ART06 w0.127: v3(22.69,95.76) 22.1,95.16 22.1,86.61 24.8,83.91 v2(25.33,83.91)
  BOTTOM w0.127: v3(22.69,95.76) 22.69,96.35 R127.2
N21015139: length 16.7
  TOP w0.127: v2(25.33,84.56) 25.65,84.24 U1.P4
  ART06 w0.127: v3(22.69,94.49) 22.69,87.19 v2(25.33,84.56)
  BOTTOM w0.127: v3(22.69,94.49) 23.37,95.16 23.37,95.89 R128.2
N21015638: length 74.7
  TOP w0.127: U1.U11 v2(24.03,80.01) ; R91.2 v1(8.13,25.02)
  ART06 w0.076: v2(24.03,80.01) 23.7,80.34 23.7,81.46 23.52,81.64 23.13,81.64 22.97,81.79
  ART06 w0.127: 22.97,81.79 22.6,82.17 16.13,82.17 15.49,81.53 12.83,81.53 10.29,78.99 10.29,70.46 8.26,68.43 8.26,47.75 5.87,45.36 5.87,32.87 8.13,30.61 v1(8.13,25.02)
N21015640: length 17
  TOP w0.076: U1.W13 22.73,78.71 20.05,78.71
  TOP w0.127: R93.2 14.35,73.91 19.15,78.71 20.05,78.71
N21015650: length 19.1
  TOP w0.127: v1(13.72,74.93) 13.21,74.42 8.76,74.42 R95.2 ; U1.V12 v2(23.38,78.71)
  ART06 w0.127: v2(23.38,78.71) 22.64,78.71 22.23,79.12 17.27,79.12 16.89,78.74 15.75,78.74 14.35,77.34 14.35,75.56 v1(13.72,74.93)
N21015652: length 20.7
  TOP w0.127: U1.V11 v2(23.38,80.01)
  ART06 w0.127: v1(13.34,79.12) 14.66,80.44 15.93,80.44 16.51,81.03 22.36,81.03 v2(23.38,80.01)
  BOTTOM w0.127: v1(13.34,79.12) 9.4,83.06 9.4,83.57 9.14,83.82 7.24,83.82 7.11,83.95 R97.2
N21015654: length 20
  TOP w0.127: U1.V10 v2(23.38,80.66)
  ART06 w0.127: v2(23.38,80.66) 23.23,80.66 22.48,81.41 16.38,81.41 15.77,80.8 14,80.8 v1(12.32,79.12)
  BOTTOM w0.127: R99.2 7.11,82.8 7.37,82.55 9.14,82.55 12.32,79.38 v1(12.32,79.12)
N21015656: length 19.1
  TOP w0.127: U1.V9 v2(23.38,81.31)
  ART06 w0.127: v2(23.38,81.31) 23.08,81.31 22.61,81.79 16.26,81.79 15.62,81.15 13.21,81.15 v1(11.18,79.12)
  BOTTOM w0.127: R101.2 7.11,80.14 8.13,79.12 v1(11.18,79.12)
N21015658: length 77.2
  TOP w0.127: U1.U10 v2(24.03,80.66) ; R103.2 v1(8.13,23.24)
  ART06 w0.076: v2(24.03,80.66) 24.03,81.51 23.7,81.84 23.7,82.14 23.55,82.3 23.11,82.3
  ART06 w0.127: v1(8.13,23.24) 7.62,23.75 7.62,30.61 5.49,32.74 5.49,45.62 7.87,48.01 7.87,68.45 9.98,70.56 9.98,79.2 12.7,81.92 15.37,81.92 16,82.55 22.73,82.55 22.99,82.3 23.11,82.3
N21015660: length 83.5
  TOP w0.127: v1(7.62,20.57) 8.13,21.08 R105.2 ; U1.T11 v2(24.68,80.01)
  ART06 w0.076: 23.62,83.19 23.88,82.93 24.26,82.93 24.35,82.84 24.35,80.34 v2(24.68,80.01)
  ART06 w0.127: v1(7.62,20.57) 6.91,21.29 6.91,30.35 4.83,32.44 4.83,45.97 6.22,47.37 6.22,51.44 7.14,52.35 7.14,68.53 9.4,70.79 9.4,79.63 12.45,82.68 15.11,82.68 15.88,83.44 23.37,83.44 23.62,83.19
N21015662: length 82.7
  TOP w0.076: U1.U9 24.03,81.31 v2(24.03,81.96)
  TOP w0.127: R107.2 v1(8.13,18.29)
  ART06 w0.076: 22.73,83.06 23.39,83.06 23.7,82.75 23.7,82.47 24.03,82.15 v2(24.03,81.96)
  ART06 w0.127: 22.73,83.06 16,83.06 15.24,82.3 12.57,82.3 9.68,79.4 9.68,70.66 7.49,68.48 7.49,52.2 6.6,51.31 6.6,47.24 5.11,45.75 5.11,32.61 7.24,30.48 7.24,21.97 8.13,21.08 v1(8.13,18.29)
N21015664: length 77.4
  TOP w0.076: 22.23,79.36 22.73,79.36 U1.W12
  TOP w0.127: v1(13.72,76.2) 15.7,76.2 18.86,79.36 22.23,79.36 ; R109.2 v1(8.13,15.62)
  ART06 w0.127: v1(8.13,15.62) 8.76,16.26 8.76,30.43 6.2,32.99 6.2,44.58 6.73,45.11 7.29,45.11 8.64,46.46 8.64,68.4 11.43,71.2 11.43,74.55 12.45,75.56 13.08,75.56 v1(13.72,76.2)
N21015666: length 92.3
  TOP w0.127: R111.2 v1(8.13,13.08) ; U1.T10 v2(24.68,80.66)
  ART06 w0.076: 24.89,82.42 25,82.31 25,80.98 v2(24.68,80.66)
  ART06 w0.127: 24.89,82.42 24.7,82.61 24.7,83.38 23.75,84.33 16.26,84.33 14.99,83.06 12.32,83.06 9.09,79.83 9.09,70.89 6.86,68.66 6.86,54.23 5.84,53.21 5.84,47.5 4.55,46.2 4.55,32.28 6.6,30.23 6.6,14.61 v1(8.13,13.08)
N21015668: length 79.9
  TOP w0.127: v1(12.7,74.93) 13.34,75.56 15.49,75.56 18.96,79.04 U1.Y12 ; R113.2 v1(9.14,11.43)
  ART06 w0.127: v1(12.7,74.93) 11.94,74.17 11.94,71.3 9.02,68.38 9.02,46.18 7.49,44.65 6.81,44.65 6.55,44.4 6.55,33.12 9.14,30.53 v1(9.14,11.43)
N21034668: length 0.5
  TOP w0.254: U1.E9 v2(32.47,81.31)
N21049023: length 4.4
  TOP w0.127: J7.1 v1(77.29,127.13)
  BOTTOM w0.127: C157.2 R31.2 77.72,127.56 v1(77.29,127.13)
N21049035: length 3.4
  TOP w0.127: J7.4 v1(71.2,124.21)
  BOTTOM w0.127: v1(71.2,124.21) 71.12,124.13 C159.2
N21049037: length 3.6
  TOP w0.127: J7.3 71.5,127.5 v1(71.25,127.25)
  BOTTOM w0.127: v1(71.25,127.25) 71.63,127.64 C161.2
N21049039: length 3.4
  TOP w0.127: v1(69.83,127.13) 69.2,127.76 J7.8
  BOTTOM w0.127: R33.2 v1(69.83,127.13)
N21049041: length 3
  TOP w0.127: v1(73.68,124.21) 73.3,123.83 J7.7
  BOTTOM w0.127: R34.2 v1(73.68,124.21)
N21049043: length 1
  BOTTOM w0.127: C160.2 R34.1
N21049045: length 1.1
  BOTTOM w0.127: R33.1 C158.2
N21090577: length 6.7
  TOP w0.254: U1.F9 v2(31.82,80.66)
  ART06 w0.254: v2(31.82,80.66) 32.23,80.25 32.75,80.25 32.94,80.44 v2(37.85,80.44)
N21140101: length 5.2
  TOP w0.127: 72.26,27.65 K1.2
N21140162: length 4.7
  TOP w0.127: R1.2 34.29,8.76 J1.1
N21140164: length 4.6
  TOP w0.127: J1.3 R2.2
N21140180: length 4.6
  TOP w0.127: 29.21,4.45 R3.2
N21140182: length 4.6
  TOP w0.127: 26.67,4.45 R4.2
N21185456: length 5.1
  TOP w0.254: U26.4 66.34,106.23 v1(66.43,106.32)
  BOTTOM w0.381: FB7.2 C226.1 C225.1 66.3,106.19 v1(66.43,106.32)
N21185461: length 4.5
  TOP w0.254: v1(66.55,108.71) 65.28,108.71 U26.9
  BOTTOM w0.381: C224.1 C223.1 66.19,108.48 66.42,108.71 v1(66.55,108.71) 67.04,108.71 FB8.2
N21191941: length 2.4
  TOP w0.127: R201.2 66.91,111.23 U26.14
N21191953: length 2.1
  TOP w0.254: U26.6 v1(66.43,107.23)
  BOTTOM w0.381: R202.2 66.32,107.34 v1(66.43,107.23)
N21192465: length 2.4
  TOP w0.127: R203.2 63.75,102.23 63.96,102.44 U26.63
N21192467: length 3.9
  TOP w0.127: U26.62 63.46,102.58 63.12,102.23 63.12,101.09 R204.2
N21192469: length 5.1
  TOP w0.127: R205.2 62.74,100.33 62.74,102.36 62.96,102.59 U26.61
N21250278: length 1.6
  TOP w0.127: R209.2 67.4,115.38 U25.8
N21252465: length 16.6
  TOP w0.076: U1.C2 33.77,85.86 33.77,86.49 33.99,86.7
  TOP w0.127: 47.37,89.79 46.74,90.42 38.23,90.42 35.05,87.25 34.54,87.25 33.99,86.7
N21252472: length 18
  TOP w0.076: U1.D2 33.12,85.86 33.12,86.49
  TOP w0.127: 47.37,92.08 38.1,92.08 33.12,87.1 33.12,86.49
N21252475: length 15.4
  TOP w0.127: U1.B1 34.66,86.74 35.05,86.74 38.35,90.04 45.97,90.04 47.37,88.65
N21252478: length 21.5
  TOP w0.102: U1.G3 31.17,85.21 v2(31.82,85.21)
  TOP w0.127: v3(34.42,89.66) 39.12,94.36 47.37,94.36
  ART06 w0.127: v2(31.82,85.21) 34.42,87.8 v3(34.42,89.66)
N21252481: length 16.2
  TOP w0.127: 47.37,90.93 38.23,90.93 35.05,87.76 34.54,87.76 33.45,86.66 U1.C1
N21252484: length 18.1
  TOP w0.127: U1.D1 32.8,87.28 38.73,93.22 47.37,93.22
N21259407: length 4.6
  TOP w0.127: 21.59,4.45 R15.2
N21259420: length 4.6
  TOP w0.127: 24.13,4.45 R12.2
N21259441: length 4.6
  TOP w0.127: 19.05,4.45 R16.2
N21259446: length 5.1
  TOP w0.127: 16.51,4.45 15.24,5.71 R17.2
N21326640: length 5
  BOTTOM w0.127: R245.1 65.41,86.36 65.09,86.04 U22.4
N21346225: length 13.1
  TOP w0.127: GPIO25.1 29.21,97.28 28.83,97.28 27.6,96.05 U1.M1
N21377535: length 2.7
  TOP w0.127: U30.H5 42.16,113.28 v2(41.27,112.39)
  BOTTOM w0.127: v2(41.27,112.39) 41.02,112.14 R47.2
N21379070: length 2
  TOP w0.076: 45.43,110.53 44.91,110.53 U30.C2
  TOP w0.127: v3(45.72,110.53) 45.43,110.53
  BOTTOM w0.127: C24.1 45.47,110.78 v3(45.72,110.53)
N21433380: length 6.3
  TOP w0.127: v2(42.55,114.81) 42.55,115.16 U30.M6
  BOTTOM w0.127: v2(42.55,114.81) 42.55,113.54 41.78,112.78 39.62,112.78 R50.2
N21453086: length 7.5
  TOP w0.127: U4.9 67.54,81.69 68.45,80.77 v1(70.99,80.77)
  BOTTOM w0.127: v1(70.99,80.77) R55.1
N21464356: length 3.4
  TOP w0.127: R141.1 6.1,68.2 J5.8
N21464369: length 2.8
  TOP w0.127: J5.10 6.86,67.31 R144.1
N21465198: length 2.2
  TOP w0.127: U1.U7 v2(24.03,82.61)
  BOTTOM w0.127: v2(24.03,82.61) 23.32,83.31 R56.2
N21620702: length 1.2
  TOP w0.086: v2(26.23,48.18) 26.15,48.18 U5.T11
  BOTTOM w0.086: v2(26.23,48.18) 26.16,48.12 R64.1
N21620763: length 1.4
  TOP w0.127: U5.A5 21.35,58.58 v2(21.42,58.58)
  BOTTOM w0.127: v2(21.42,58.58) 21.51,58.67 R66.1
N21620853: length 1.9
  TOP w0.086: v2(18.22,54.03) 18.3,54.03 U5.G2
  BOTTOM w0.086: R72.1 R63.1 18.29,53.97 v2(18.22,54.03)
N21621296: length 1.6
  TOP w0.086: v2(38.13,48.18) 38.2,48.18 U7.T11
  BOTTOM w0.086: R68.1 38.18,48.18 v2(38.13,48.18)
N21621349: length 1.4
  TOP w0.127: U7.A5 34.05,58.58 v2(34.12,58.58)
  BOTTOM w0.127: v2(34.12,58.58) 34.21,58.67 R69.1
N21621402: length 3.3
  TOP w0.086: v2(31.72,54.68) 31.65,54.68 U7.G2
  BOTTOM w0.086: R67.1 R73.1 31.37,53.72 31.37,54.33 v2(31.72,54.68)
N21701166: length 3.6
  BOTTOM w0.127: R82.2 C10.1 62.85,132.72 J18.1
N21701169: length 3.6
  BOTTOM w0.127: J18.2 61.6,132.72 C305.1 R84.2
N21732896: length 3.6
  TOP w0.127: R86.2 C306.1 J19.1
N21732906: length 3.6
  TOP w0.127: R90.2 C307.1 J19.2
N21734873: length 2.1
  TOP w0.127: U16.20 54.88,121.56 C309.2
N21734889: length 1.9
  TOP w0.127: C310.2 54.49,122.05 U16.19
N21735099: length 2
  TOP w0.127: U16.16 54.75,123.55 C311.2
N21735109: length 2
  TOP w0.127: C312.2 54.6,123.06 U16.17
N21746916: length 3.4
  TOP w0.127: 67.69,134.49 68.71,134.49 U29.1
N21763238: length 2.8
  TOP w0.305: Q2.1 R76.2 R137.2
N21763240: length 3
  TOP w0.305: Q2.3 23.05,36.83 R23.1 R78.1
N21763433: length 1.7
  TOP w0.305: Q1.1 20.77,35.25 R78.2
N21776900: length 2
  TOP w0.127: U34.8 61.92,100.53 v1(62.23,100.84)
  BOTTOM w0.127: R146.2 v1(62.23,100.84)
N21777075: length 20.2
  TOP w0.127: U34.12 59.98,101.57 59.69,101.85 v1(58.8,101.85)
  ART06 w0.127: v1(71.25,90.17) 68.96,92.46 67.94,92.46 58.8,101.6 v1(58.8,101.85)
  BOTTOM w0.127: R147.1 v1(71.25,90.17)
N21777236: length 3.8
  TOP w0.127: GPIO1.1 58.17,102.36 59.94,102.36 60.38,101.93 U34.11
N21777269: length 3
  TOP w0.127: J22.1 60.58,98.17 60.38,98.37 U34.4
N21792244: length 4.5
  TOP w0.254: v1(52.07,37.08) 52.46,36.7 U35.10
  TOP w0.305: C333.1 v1(52.07,37.08)
  BOTTOM w0.305: C333.1 v1(52.07,37.08)
N21792661: length 4.5
  TOP w0.254: v1(53.21,37.08) 52.96,36.83 U35.9
  TOP w0.305: C334.1 v1(53.21,37.08)
  BOTTOM w0.305: C334.1 v1(53.21,37.08)
N21792699: length 4.1
  TOP w0.254: U35.22 52.95,28.33 v1(53.21,28.07)
  TOP w0.381: C335.1 v1(53.21,28.07)
  BOTTOM w0.381: C335.1 v1(53.21,28.07)
N21792731: length 4.2
  TOP w0.254: v1(52.07,28.07) 52.45,28.45 U35.21
  TOP w0.381: C336.1 v1(52.07,28.07)
  BOTTOM w0.381: C336.1 v1(52.07,28.07)
N21793143: length 3.1
  TOP w0.254: 56.52,32.13 U35.3
  TOP w0.305: 56.52,32.13 57.53,32.13 R277.2
N21793155: length 3
  TOP w0.254: R278.2 57.68,33.63 U35.6
N21799819: length 6.2
  TOP w0.254: 49.03,34.79 50.18,33.64 U35.13
  TOP w0.305: R280.1 R279.1 48.64,35.18 49.03,34.79
N21806853: length 1.8
  TOP w0.127: U36.8 53.41,107.37 53.72,107.06 R284.1
N21806875: length 3.6
  TOP w0.381: R286.1 R285.1 U37.2
N21819738: length 1.4
  TOP w0.381: LED1.1 R19.2
N21842446: length 4.8
  TOP w0.305: U38.1 59.7,75.7 58.93,74.93 57.78,74.93 57.78,77.34
N21842448: length 9.6
  TOP w0.305: 58.04,82.04 56.26,82.04 55.63,81.41 55.63,77.22 R294.2 C382.2
N21842466: length 3.5
  TOP w0.305: R293.2 58.29,73.53 60.2,75.44 U38.2
N21842648: length 0.8
  TOP w0.305: U38.6 60.7,78.58
N21859306: length 8.2
  TOP w0.127: K4.2 74.68,34.67 71.69,34.67 Q5.1
N21859320: length 8.8
  TOP w0.127: K4.1 75.31,33.31 75.31,31.88 72.26,28.83
N21859857: length 1.6
  TOP w0.305: 21.72,24.77 21.72,25.4 22.1,25.78 22.48,25.78
N21859915: length 3.9
  TOP w0.305: U9.4 27.7,24.12 28.32,23.5 C129.1 R143.2
N21859948: length 3.6
  TOP w0.381: U9.2 R177.2 R178.1
N21888386: length 5.4
  TOP w0.254: U35.5 56.78,33.14 v1(57.02,32.89)
  BOTTOM w0.305: v1(57.02,32.89) 57.15,32.89 R266.2 C320.2 R267.1
N21888866: length 7.4
  TOP w0.254: U35.14 49.8,33.14 v1(48.77,34.16)
  BOTTOM w0.305: v1(48.77,34.16) 47.75,35.18 R268.2 R269.1 C323.2
N21889896: length 5.5
  TOP w0.381: v1(58.8,29.21) 58.8,25.78
  BOTTOM w0.381: R270.1 C332.1 v1(58.8,29.21)
N21889964: length 5.4
  TOP w0.254: v1(56.77,31.24) 56.38,31.63 U35.2
  BOTTOM w0.381: R271.1 R270.2 ; R270.2 v1(56.77,31.24) ; R270.2 C332.2
N21891772: length 5.3
  TOP w0.254: v1(48.77,30.99) 49.41,31.63 U35.17
  BOTTOM w0.305: v1(48.77,30.99) 48.64,30.99 R276.2 C328.2 R275.2
N21913022: length 3.5
  TOP w0.381: C402.1 R304.2 23.05,18.1 U39.3

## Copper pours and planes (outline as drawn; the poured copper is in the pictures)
AVDD_1V8 on TOP: 44.07,44.2 43.94,44.32 43.94,47.5 44.07,47.62 46.1,47.62 46.23,47.5 46.23,44.32 46.1,44.2
AVDD_1V8 on BOTTOM: 70.23,104.01 70.23,119.25 69.72,119.76 64.01,119.76 63.63,120.14 63.63,123.32 63.88,123.57 65.66,123.57 65.91,123.32 65.91,122.17 66.8,121.28 74.17,121.28 74.68,120.78 76.71,120.78 76.83,120.65 76.83,119.38 76.71,119.25 72.26,119.25 72.14,119.13 72.14,99.57 63.69,91.12 63.69,87.31 58.29,81.92 58.29,57.02 46.23,44.96 43.43,44.96 43.31,45.09 43.31,51.05 53.85,61.59 53.85,87.63
AVDD_1V8 on ART06: 47.88,81.15 48.64,80.39 55.24,80.39 55.37,80.52 55.37,83.57 55.24,83.69 45.97,83.69 45.59,84.07 43.43,84.07 42.8,84.71 40.77,84.71 40.26,85.22 36.45,85.22 34.92,83.69 32.26,83.69 31.5,82.93 31.5,82.3 31.62,82.17 40.13,82.17 41.15,81.15
AVDD_PLL_0V8 on TOP: 62.99,50.67 62.99,48.51 62.87,48.39 60.96,48.39 60.83,48.51 60.83,52.7 63.37,55.24 63.37,62.36 58.55,67.18 54.1,67.18 51.44,69.85 51.44,70.74 51.56,70.87 53.47,70.87 55.12,69.22 60.2,69.22 65.53,63.88 65.53,53.21
AVDD_PLL_0V8 on BOTTOM: 34.67,77.6 32.77,77.6 32,78.36 31.62,78.36 31.5,78.49 31.5,79.12 35.31,79.12 35.94,78.49 37.34,78.49 37.47,78.36 46.61,78.36 53.21,71.75 53.21,69.09 53.09,68.96 50.29,68.96 42.67,76.58 35.69,76.58
GND on TOP: 60.33,60.96 60.33,58.67 60.2,58.55 57.28,58.55 57.15,58.67 57.15,61.85 57.28,61.98 59.31,61.98
GND on TOP: 71.63,19.68 74.55,19.68 74.68,19.56 74.68,17.02 74.55,16.89 71.63,16.89 71.5,17.02 71.5,19.56
GND on TOP: 71.63,11.05 74.55,11.05 74.68,10.92 74.68,8.51 74.55,8.38 71.63,8.38 71.5,8.51 71.5,10.92
GND on TOP: 67.56,139.19 70.99,139.19 71.12,139.06 71.12,137.92 70.99,137.79 67.56,137.79 67.44,137.92 67.44,139.06
GND on TOP: 19.05,21.08 21.08,21.08 21.21,20.95 21.21,18.67 21.08,18.54 19.05,18.54 18.92,18.67 18.92,20.95
GND on TOP: 65.41,97.92 65.41,101.6 65.53,101.73 67.44,101.73 67.56,101.6 67.56,100.58 67.44,100.46 66.29,100.46 66.17,100.33 66.17,98.81 66.29,98.68 68.2,98.68 68.33,98.81 68.33,99.82 68.45,99.95 69.47,99.95 69.6,100.08 69.6,101.73 69.72,101.85 70.1,101.85 70.23,101.73 70.23,97.92 70.1,97.79 65.53,97.79
GND on TOP: 61.85,92.33 62.36,92.84 62.36,94.11 62.23,94.23 60.45,94.23 60.33,94.11 60.33,92.84 60.83,92.33 60.83,89.66 60.96,89.53 61.72,89.53 61.85,89.66
GND on TOP: 55.5,84.71 55.63,84.84 57.53,84.84 57.66,84.71 57.66,82.68 57.53,82.55 55.63,82.55 55.5,82.68
GND on TOP: 48.9,71.5 48.77,71.37 45.85,71.37 45.72,71.5 45.72,72.77 45.85,72.9 48.77,72.9 48.9,72.77
GND on TOP: 50.16,76.83 50.04,76.96 50.04,78.87 50.29,79.12 51.69,79.12 51.82,78.99 51.82,77.72 51.94,77.6 53.72,77.6 53.85,77.72 53.85,79.38 53.34,79.88 52.32,79.88 52.2,80.01 52.2,81.53 52.07,81.66 50.04,81.66 49.78,81.92 49.78,84.07 50.04,84.33 54.36,84.33 54.48,84.2 54.48,76.96 54.36,76.83
GND on TOP: 57.03,104.8 56.9,104.92 56.9,112.03 57.03,112.16 64.27,112.16 64.4,112.03 64.4,104.92 64.27,104.8
GND on TOP: 25.53,28.32 25.4,28.45 22.48,28.45 22.35,28.57 22.35,30.35 22.48,30.48 27.69,30.48 27.81,30.35 27.81,26.16 27.69,26.04 26.67,26.04 26.54,25.91 26.54,23.75 26.67,23.62 27.56,23.62 27.69,23.5 27.69,22.99 27.56,22.86 24.51,22.86 24.38,22.99 24.38,23.5 24.51,23.62 25.4,23.62 25.53,23.75
GND on TOP: 70.87,109.35 74.42,109.35 74.55,109.22 74.55,107.19 74.42,107.06 70.87,107.06 70.74,107.19 70.74,109.22
GND on TOP: 71.88,66.17 74.42,66.17 74.55,66.04 74.55,64.26 74.42,64.14 71.88,64.14 71.75,64.26 71.75,66.04
GND on TOP: 43.43,30.1 39.62,30.1 39.5,30.23 39.5,32.77 39.62,32.89 43.43,32.89 43.56,32.77 43.56,30.23
GND on TOP: 71.88,70.36 74.68,70.36 74.8,70.23 74.8,68.45 74.68,68.33 71.88,68.33 71.75,68.45 71.75,70.23
GND on TOP: 71.37,78.36 74.42,78.36 74.55,78.23 74.55,76.96 73.79,76.2 71.37,76.2 71.25,76.33 71.25,78.23
GND on TOP: 38.99,36.96 38.99,42.29 40.64,43.94 40.64,58.29 40.77,58.42 43.31,58.42 43.43,58.29 43.43,36.96 43.31,36.83 39.12,36.83
GND on TOP: 51.44,33.78 53.98,33.78 54.1,33.66 54.1,31.11 53.98,30.99 51.44,30.99 51.31,31.11 51.31,33.66
GND on TOP: 60.96,130.05 61.09,129.92 63.37,129.92 63.5,130.05 63.5,131.95 63.63,132.08 64.77,132.08 64.9,131.95 64.9,129.03 61.72,125.86 57.91,125.86 57.78,125.98 57.78,132.08 57.91,132.21 60.83,132.21 60.96,132.08
GND on TOP: 67.56,96.52 67.56,94.36 67.44,94.23 65.28,94.23 65.15,94.36 65.15,96.52 65.28,96.65 67.44,96.65
GND on TOP: 77.85,94.36 77.72,94.23 74.17,94.23 74.04,94.36 74.04,97.66 74.17,97.79 77.6,97.79 77.85,97.54
GND on TOP: 57.15,123.95 59.69,123.95 59.82,123.83 59.82,121.28 59.69,121.16 57.15,121.16 57.02,121.28 57.02,123.83
GND on TOP: 0.64,105.03 0.64,127.38 1.02,127.76 7.87,127.76 8.13,127.51 8.13,105.16 7.62,104.65 1.02,104.65
GND on TOP: 78.61,79.63 78.49,79.5 74.55,79.5 74.42,79.63 74.42,81.92 74.55,82.04 78.49,82.04 78.61,81.92
GND on TOP: 58.67,77.22 58.8,77.34 63.25,77.34 63.37,77.22 63.37,69.72 63.25,69.6 61.59,69.6 61.47,69.72 61.47,75.18 61.09,75.56 61.09,76.2 60.96,76.33 58.8,76.33 58.67,76.45
GND on TOP: 65.02,81.03 67.56,81.03 68.07,80.52 68.07,79.76 67.06,78.74 65.15,78.74 64.9,78.99 64.9,80.9
GND on TOP: 30.61,17.27 30.73,17.14 30.73,15.37 30.61,15.24 27.43,15.24 27.3,15.37 27.3,17.14 27.43,17.27
GND on TOP: 42.67,85.34 44.32,85.34 44.96,84.71 44.96,82.8 44.83,82.68 42.67,82.68 42.55,82.8 42.55,85.22
GND on TOP: 42.04,17.53 41.91,17.65 41.91,21.97 42.04,22.1 49.78,22.1 49.91,22.23 49.91,26.29 50.04,26.42 51.44,26.42 51.56,26.29 51.56,25.53 51.69,25.4 53.59,25.4 53.72,25.53 53.72,26.16 53.85,26.29 55.12,26.29 55.24,26.16 55.24,22.23 55.37,22.1 59.44,22.1 59.56,21.97 59.56,18.8 59.44,18.67 55.5,18.67 55.37,18.8 55.37,20.45 55.24,20.57 47.12,20.57 46.99,20.45 46.99,17.65 46.86,17.53
GND on TOP: 44.83,76.71 43.56,76.71 43.43,76.83 43.43,78.11 43.31,78.23 42.42,78.23 42.29,78.36 42.29,80.39 42.42,80.52 43.81,80.52 43.94,80.39 43.94,79.63 45.09,78.49 45.09,76.96
GND on TOP: 41.15,72.14 42.55,72.14 43.05,71.63 44.07,71.63 44.2,71.5 44.2,69.34 44.07,69.22 41.15,69.22 41.02,69.34 41.02,72.01
GND on TOP: 50.29,59.18 50.16,59.31 45.72,59.31 45.59,59.44 45.59,63.37 45.72,63.5 50.67,63.5 51.69,64.52 52.83,64.52 52.96,64.39 52.96,45.97 53.59,45.34 53.59,40.89 53.98,40.51 55.63,40.51 55.75,40.39 55.75,38.86 55.63,38.73 53.98,38.73 53.85,38.86 53.85,39.5 53.72,39.62 51.56,39.62 51.44,39.5 51.44,38.99 51.31,38.86 50.42,38.86 50.29,38.99
GND on TOP: 74.68,98.93 71.75,98.93 71.63,99.06 71.63,101.09 71.75,101.22 74.8,101.22 74.93,101.09 74.93,99.19
GND on TOP: 4.19,85.09 4.19,87.5 4.32,87.63 5.84,87.63 6.99,86.49 6.99,85.34 6.6,84.96 4.32,84.96
GND on TOP: 71.88,58.29 74.55,58.29 74.68,58.17 74.68,56.39 74.55,56.26 71.88,56.26 71.75,56.39 71.75,58.17
